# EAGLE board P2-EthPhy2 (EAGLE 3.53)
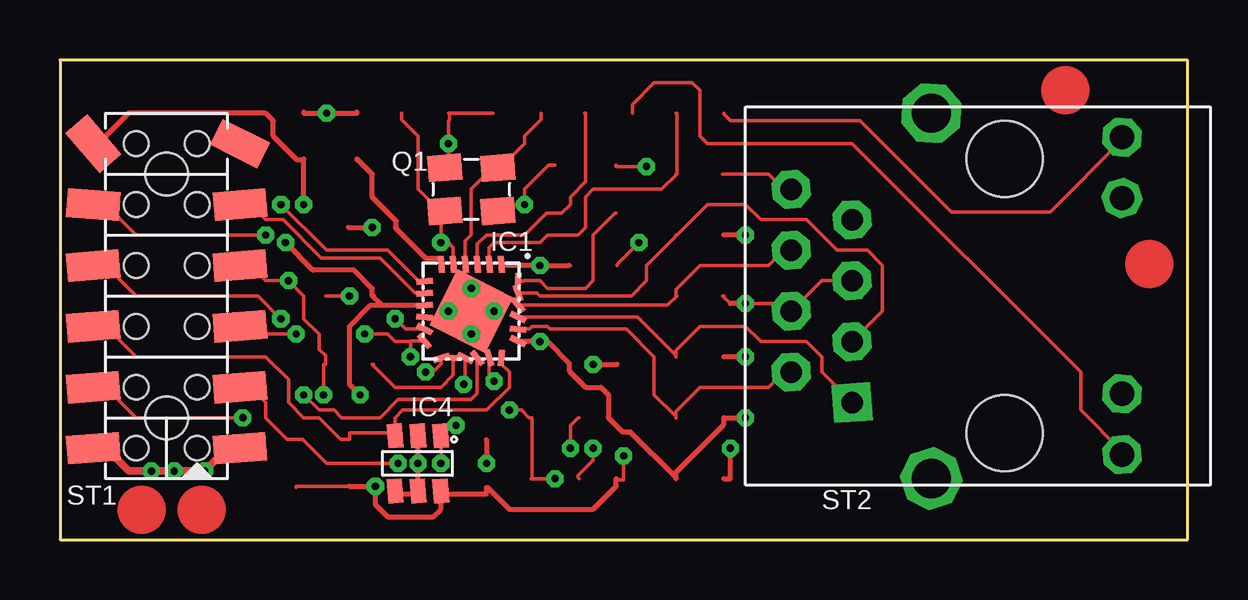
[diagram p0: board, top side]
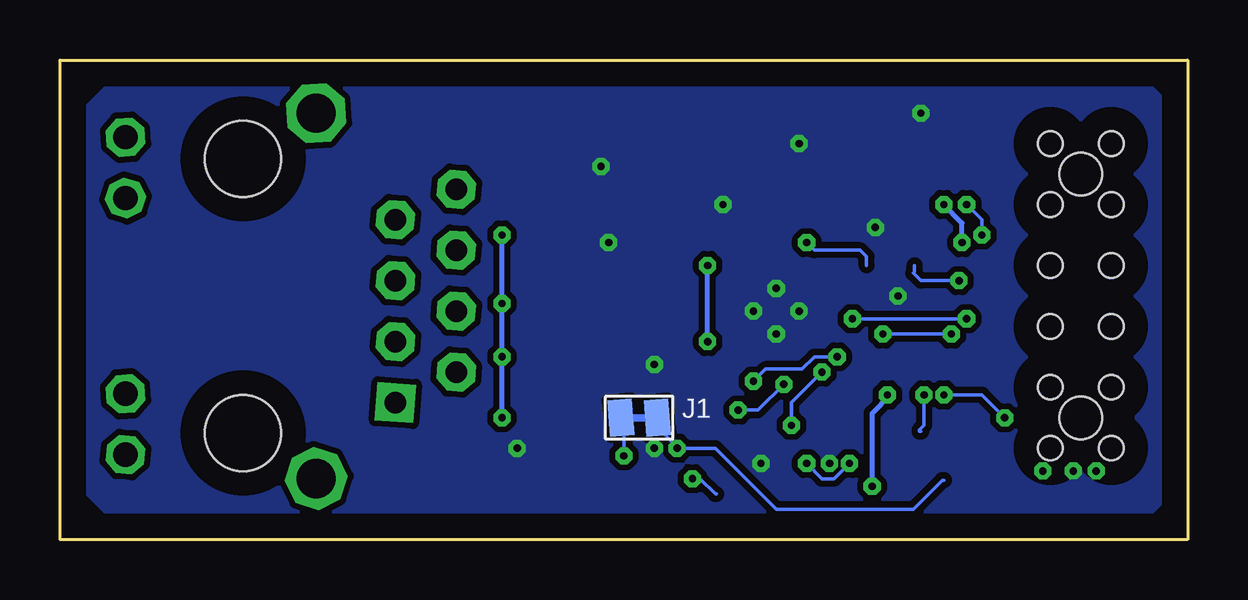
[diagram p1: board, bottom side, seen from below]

Size 47 x 20 mm. Coordinates in mm from the lower left corner, seen from the top.
Outline: 0,0 47,0 47,20 0,20 0,0
Copper layers used: Top, Bottom

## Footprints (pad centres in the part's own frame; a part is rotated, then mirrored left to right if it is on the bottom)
N-24 = smd 2.6 x 2.6 rotated 116.9:  0,0 | smd 0.25 x 0.7 rotated 4.6:  0.25,-1.95 | smd 0.25 x 0.7 rotated 4.5:  -0.25,-1.95 | smd 0.25 x 0.7 rotated 4.4:  -0.75,-1.95 | smd 0.25 x 0.7 rotated 4.3:  -1.25,-1.95 | smd 0.25 x 0.7 rotated 4.7:  0.75,-1.95;  1.25,-1.95 | smd 0.7 x 0.25 rotated 4.8:  1.95,-1.25 | smd 0.7 x 0.25 rotated 4.9:  1.95,-0.75 | smd 0.7 x 0.25 rotated 49.3:  1.95,1.25 | smd 0.7 x 0.25 rotated 26.8:  1.95,0.75 | smd 0.7 x 0.25 rotated 4.3:  1.95,0.25 | smd 0.7 x 0.25 rotated 5:  1.95,-0.25 | smd 0.25 x 0.7 rotated 71.8:  1.25,1.95 | smd 0.25 x 0.7 rotated 94.3:  0.75,1.95 | smd 0.25 x 0.7 rotated 116.8:  0.25,1.95 | smd 0.25 x 0.7 rotated 139.3:  -0.25,1.95 | smd 0.7 x 0.25 rotated 4.4:  -1.95,0.75 | smd 0.7 x 0.25 rotated 206.8:  -1.95,1.25 | smd 0.25 x 0.7 rotated 184.3:  -1.25,1.95 | smd 0.25 x 0.7 rotated 161.8:  -0.75,1.95 | smd 0.7 x 0.25 rotated 26.9:  -1.95,0.25 | smd 0.7 x 0.25 rotated 49.4:  -1.95,-0.25 | smd 0.7 x 0.25 rotated 71.9:  -1.95,-0.75 | smd 0.7 x 0.25 rotated 94.4:  -1.95,-1.25
T23-6 = smd 0.635 x 1.016 rotated 4.7:  0,1.15;  -0.95,1.15 | smd 0.635 x 1.016 rotated 4.6:  0.95,1.15 | smd 0.635 x 1.016 rotated 4.3:  -0.95,-1.15 | smd 0.635 x 1.016 rotated 4.4:  0,-1.15 | smd 0.635 x 1.016 rotated 4.5:  0.95,-1.15
MP2-NC = smd 1.016 x 1.524 rotated 4.3:  -0.762,0 | smd 1.016 x 1.524 rotated 4.4:  0.762,0
D3225 = smd 1.4 x 1.1 rotated 4.6:  -1.1,0.9 | smd 1.4 x 1.1 rotated 4.3:  -1.1,-0.9 | smd 1.4 x 1.1 rotated 4.4:  1.1,-0.9 | smd 1.4 x 1.1 rotated 4.5:  1.1,0.9
06-SBE = smd 1.2 x 2.2 rotated 4.3:  -6.35,-3.058;  3.81,3.058 | smd 1.2 x 2.2 rotated 4.4:  -6.35,3.058 | smd 1.2 x 2.2 rotated 4.5:  -3.81,-3.058 | smd 1.2 x 2.2 rotated 4.6:  -3.81,3.058 | smd 1.2 x 2.2 rotated 4.7:  -1.27,-3.058;  -1.27,3.058 | smd 1.2 x 2.2 rotated 4.8:  1.27,-3.058 | smd 1.2 x 2.2 rotated 4.9:  1.27,3.058 | smd 1.2 x 2.2 rotated 5:  3.81,-3.058 | smd 1.2 x 2.2 rotated 26.8:  6.35,-3.058 | smd 1.2 x 2.2 rotated 49.3:  6.35,3.058 | hole 1.016: -6.35,-1.27; -3.81,-1.27; -1.27,-1.27; 1.27,-1.27; 3.81,-1.27; 6.35,-1.27; 6.35,1.27; 3.81,1.27; 1.27,1.27; -1.27,1.27; -3.81,1.27; -6.35,1.27 | hole 1.778: -5.08,0; 5.08,0
45HR5C = drill 0.89 pad 1.6 octagon:  8.89,0.635;  6.35,1.905;  6.35,-0.635;  8.89,-1.905;  8.89,3.175;  6.35,-3.175;  8.89,-4.445 | drill 0.89 pad 1.6 square:  6.35,4.445 | drill 1.63 pad 2.184 octagon:  3.05,7.62;  3.05,-7.62 | drill 1.016 pad 1.6 octagon:  -4.9,6.62;  -4.9,4.08;  -4.9,-4.08;  -4.9,-6.62 | hole 3.175: 0,5.715; 0,-5.715

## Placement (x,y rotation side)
C1  100n  [05]  20.64,2.54 180 top
C2  15p  [05]  15.24,17.78 180 top
C3  15p  [05]  19.05,17.78 0 top
C4  100n  [05]  26.67,2.54 180 top
C5  10u  [05]  10.16,16.83 270 top
C6  100n  [05]  12.06,10.16 0 top
C7  100n  [05]  22.23,7.3 180 top
C8  100n  [05]  22.23,11.43 180 top
C9  470p  [05]  13.02,13.02 0 top
C10  10u  [05]  12.38,16.83 270 top
C11  100n  [05]  17.78,3.17 270 top
D1  dnp  [T-23]  11.11,3.49 0 bottom
IC1  LAN8720  [N-24]  17.14,9.53 180 top
IC4  24AA025E48  [T23-6]  14.92,3.17 180 top
J1  ResPU  [MP2-NC]  22.86,5.08 180 bottom
L1  FeBead  [05]  23.5,3.49 90 top
Q1  25M  [D3225]  17.14,14.61 0 top
R1  10k  [05]  20.64,5.08 0 top
R2  12k  [05]  23.18,14.61 270 top
R3  27R  [05]  12.06,7.3 180 top
R4  dnp  [05]  12.38,11.43 180 bottom
R5  330R  [05]  22.86,17.78 0 top
R6  330R  [05]  26.67,17.78 0 top
R7  49R9  [05]  26.67,5.08 0 top
R8  49R9  [05]  26.67,7.62 0 top
R9  49R9  [05]  26.67,10.16 0 top
R10  49R9  [05]  26.67,12.7 0 top
R11  10k  [05]  26.67,15.24 180 top
R12  10k  [05]  20.64,14.61 270 top
R13  dnp  [05]  20.64,1.91 0 bottom
R21  10k  [05]  9.84,3.17 90 top
R66  10k  [05]  12.06,3.17 270 top
ST1  P2Eval  [06-SBE]  4.45,10.16 90 top
ST2  RJ45-HR05  [45HR5C]  39.37,10.16 180 top
U$6  [DU-2RM]  5.91,1.25 0 top
U$8  [DU-2RM]  41.91,18.75 0 top
U$9  [DU-2RT]  3.4,1.25 0 top
U$10  [DU-2RT]  45.41,11.5 0 top

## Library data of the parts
C1-C11 D1 L1 R1-R13 R21 R66 = SMD
IC1 IC4 = SMD-IC
J1 U$6 U$8-U$10 = SMD-SPC
Q1 = Quartz
ST1 = PINHEAD
ST2 = CONNECT

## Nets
+3,3V: C5. C6. C11. IC1. IC4. J1. L1. R21. R66. ST1.
/RES: C1. IC1. R1. R13.
C50M: D1. R3. R4. ST1.
CRSDV: IC1. ST1.
ERX+: IC1. R10. ST2.
ERX-: IC1. R9. ST2.
ETX+: IC1. R8. ST2.
ETX-: IC1. R7. ST2.
GND: C1. C2. C3. C4. C5. C6. C7. C8. C9. C10. C11. IC1. IC4. Q1. R2. R11. R12. R13. ST1. ST2.
LEDG: IC1. R5. R12.
LEDY: IC1. R6. R11.
MDC: IC1. IC4. R21. ST1.
N$1: D1. J1. R1.
N$3: R6. ST2.
N$6: R5. ST2.
N$18: C3. IC1. Q1.
N$40: IC1. R2.
RCLK: IC1. R3.
RXD0: IC1. ST1.
RXD1: IC1. ST1.
TXD0: IC1. ST1.
TXD1: IC1. IC4. R66. ST1.
TXEN: IC1. ST1.
VDD: C4. C7. C8. IC1. L1. R7. R8. R9. R10. ST2.
VECR: C9. C10. IC1.
XI25: C2. IC1. Q1. R4.

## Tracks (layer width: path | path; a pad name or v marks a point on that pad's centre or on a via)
+3,3V  (via drill 0.3 pad 0.61)
  Top 0.152: 23.23,2.49 23.5,2.49 v23.5,3.49 | 12.06,2.17 12.06,2.22 9.84,2.22 9.84,2.17
  Top 0.203: 13.02,10.16 13.06,10.16 | 13.4,9.78 15.2,9.78 | 13.4,9.78 13.02,10.16 | 15.88,1.91 17.78,1.91 17.78,2.17 17.83,2.17 18.73,1.27 22.23,1.27 23.18,2.22 23.18,2.54 23.23,2.49 | IC4. 15.87,1.91 15.88,1.91 | 15.88,1.91 15.88,1.27 15.56,0.95 13.65,0.95 13.14,1.46 v13.14,2.22 12.06,2.22 | 13.02,10.16 13.02,10.48 12.26,11.24 10.54,11.24 v9.4,12.38 | v10.16,13.97 10.16,15.88 10.11,15.83 10.16,15.83 9.89,15.83 8.89,16.83 8.89,17.46 8.57,17.78 2.86,17.78 1.59,16.51 ST1. | 13.4,9.78 12.95,9.78 12.06,8.89 12.06,6.48 v12.51,6.03
  Bottom 0.152: J1. 23.5,5.08 v23.5,3.49
  Bottom 0.203: v9.4,12.38 9.4,13.21 v10.16,13.97 | v13.14,2.22 13.14,5.27 12.38,6.03 v12.51,6.03
/RES  (via drill 0.3 pad 0.61)
  Top 0.152: 16.89,7.58 16.89,6.54 v16.83,6.48 | v20.64,2.54 19.64,2.54 19.68,2.54 19.68,5.08 19.64,5.08 19.56,5.08 19.24,5.4 v18.73,5.4
  Bottom 0.152: v18.73,5.4 17.91,5.4 v16.83,6.48 | v20.64,2.54 20.32,2.54 19.68,1.91 19.64,1.91
C50M  (via drill 0.3 pad 0.61)
  Top 0.152: 7.5,11.43 7.94,11.43 8.57,10.79 v9.53,10.79 10.16,10.16 10.16,9.21 10.79,8.57 10.79,7.94 11.06,7.67 11.06,7.3 10.99,7.3 v10.99,6.03
  Bottom 0.152: 11.38,11.43 11.38,11.16 11.43,11.11 11.11,10.79 v9.53,10.79 | 11.11,4.51 11.18,4.51 11.18,4.57 10.99,4.76 v10.99,6.03
CRSDV  (via drill 0.3 pad 0.61)
  Top 0.152: 15.2,8.78 14.4,8.78 v13.97,9.21 | v9.21,9.21 8.26,10.16 3.17,10.16 1.91,11.43 1.39,11.43
  Bottom 0.152: v9.21,9.21 v13.97,9.21
ERX+
  Top 0.152: 33.02,8.26 34.29,9.53 34.29,11.43 33.66,12.06 32.38,12.06 31.11,13.34 29.21,13.34 28.57,13.97 26.99,13.97 25.72,12.7 25.67,12.7 25.67,12.65 24.45,11.43 24.45,10.79 23.81,10.16 20,10.16 19.89,10.28 19.09,10.28
ERX-
  Top 0.152: 30.48,12.06 30.16,12.06 29.53,11.43 26.67,11.43 25.67,10.43 25.67,10.16 25.72,10.16 25.33,9.78 19.09,9.78
ETX+
  Top 0.152: 33.02,5.71 31.75,6.99 31.75,7.62 31.11,8.26 29.21,8.26 28.57,8.89 26.67,8.89 25.67,7.89 25.67,7.62 25.67,7.67 24.06,9.28 19.09,9.28
ETX-
  Top 0.152: 30.48,6.99 30.16,6.99 29.53,6.35 26.67,6.35 25.67,5.35 25.67,5.08 25.67,5.13 24.77,6.03 24.77,7.62 23.61,8.78 20.43,8.78 20.32,8.89 19.68,8.89 19.57,8.78 19.09,8.78
GND  (via drill 0.3 pad 0.61)
  Top 0.152: 16.05,15.51 16.14,15.51 16.19,15.56 v16.19,16.51 16.19,17.46 16.24,17.51 16.24,17.78 | 18.25,13.71 18.47,13.71 18.73,13.97 v19.37,13.97 19.37,14.61 20.37,15.61 20.64,15.61 | 16.24,17.78 16.19,17.78 | 16.24,17.78 18.05,17.78 | 30.48,14.61 30.16,14.61 29.53,15.24 27.67,15.24 27.62,15.24 | 23.18,15.61 23.18,15.56 v24.45,15.56 | 23.23,11.43 23.23,11.48 v24.13,12.38 | 11.06,10.16 v12.06,10.16 | 21.64,2.54 21.59,2.59 21.59,2.67 22.23,3.3 v22.23,3.81
  Top 0.203: v22.23,7.3 23.23,7.3 | 27.67,2.54 27.94,2.54 v27.94,3.81 | 12.02,13.02 v13.02,13.02 | 12.38,17.83 12.38,17.78 v11.11,17.78 10.16,17.78 10.16,17.83 | 14.92,4.33 v14.92,3.17 14.92,2.02 14.92,1.91 13.97,1.91 13.97,2.02 | 17.78,4.17 v17.78,3.17 | 17.14,9.53 v16.19,9.53
  Top 0.305: 1.39,3.81 1.91,3.81 2.86,2.86 v3.81,2.86 v4.76,2.86 v6.03,2.86 6.99,3.81 7.5,3.81
  other vias: 17.14,10.48 18.1,9.53 17.14,8.57
  pour Bottom (isolate 0.254): 1.68,19 0.68,18 0.68,2 1.68,1 44.91,1 45.91,2 45.91,18 44.91,19
LEDG
  Top 0.152: 17.39,11.47 17.39,12.31 17.78,12.7 19.37,12.7 20.27,13.61 20.64,13.61 20.91,13.61 21.27,13.97 21.27,14.29 21.91,14.92 21.91,17.78 21.86,17.78
LEDY
  Top 0.152: 17.89,11.47 17.89,12.18 18.1,12.38 20,12.38 20.32,12.7 21.59,12.7 21.91,13.02 21.91,14.29 22.23,14.61 25.08,14.61 25.72,15.24 | 25.72,15.24 25.67,15.24 | 25.67,17.78 25.72,17.78 25.72,15.24
MDC  (via drill 0.3 pad 0.61)
  Top 0.152: v16.51,4.76 15.88,4.76 15.88,4.45 15.87,4.44 15.87,4.33 15.87,4.13 15.88,4.13 v15.88,3.17 | v15.24,6.99 15.56,6.99 15.89,7.32 15.89,7.58 | v14.1,3.17 11.11,3.17 10.11,4.17 9.84,4.17 9.48,4.17 8.57,5.08 8.57,5.71 7.94,6.35 7.5,6.35
  Bottom 0.152: v16.51,4.76 16.51,5.71 v15.24,6.99 | v14.1,3.17 14.73,2.54 15.24,2.54 v15.88,3.17
N$1  (via drill 0.3 pad 0.61)
  Top 0.152: 21.64,5.08 21.59,5.08 21.27,4.76 v21.27,3.81
  Bottom 0.152: 10.15,2.48 10.22,2.48 11.43,1.27 17.14,1.27 19.68,3.81 v21.27,3.81 21.27,3.87 22.1,4.7 22.1,5.08
N$3
  Top 0.152: ST2. 44.27,16.65 41.27,13.65 37.15,13.65 33.34,17.46 27.94,17.46 27.67,17.73 27.67,17.78
N$6
  Top 0.152: 23.86,17.78 23.86,18.14 24.77,19.05 26.35,19.05 26.67,18.73 26.67,16.83 26.99,16.51 33.02,16.51 42.55,6.99 42.55,5.4 44.27,3.67 44.27,3.54
N$18
  Top 0.152: 16.89,11.47 16.89,12.45 17.14,12.7 17.14,14.61 18.05,15.51 Q1. 18.36,15.51 19.37,16.51 19.37,16.83 20.05,17.51 20.05,17.78
N$40
  Top 0.152: 23.18,13.61 23.13,13.61 22.23,12.7 22.23,10.79 21.91,10.48 20.32,10.48 20,10.79 19.37,10.79 19.35,10.78 IC1.
RCLK
  Top 0.152: 16.39,7.58 16.39,6.87 15.88,6.35 13.97,6.35 13.02,7.3 13.06,7.3
RXD0
  Top 0.152: 15.2,10.28 14.81,10.28 13.34,11.75 10.89,11.75 9.3,13.34 8.57,13.34 7.94,13.97 7.5,13.97
RXD1  (via drill 0.3 pad 0.61)
  Top 0.152: 15.2,10.78 14.94,10.78 13.65,12.06 11.11,12.06 v9.21,13.97 | v8.57,12.7 3.17,12.7 1.91,13.97 1.39,13.97
  Bottom 0.152: v9.21,13.97 8.57,13.34 v8.57,12.7
TXD0  (via drill 0.3 pad 0.61)
  Top 0.152: 17.89,7.58 17.89,6.81 v18.1,6.6 | 14.61,8.26 v14.61,7.62 | 15.2,8.28 14.62,8.28 14.61,8.26 | 14.61,8.26 13.97,8.26 13.65,8.57 v12.7,8.57 | 7.5,8.89 7.49,8.89 7.81,8.57 v9.84,8.57
  Bottom 0.152: v18.1,6.6 17.59,7.11 16.07,7.11 15.56,7.62 v14.61,7.62 | v9.84,8.57 v12.7,8.57
TXD1
  Top 0.152: 18.39,7.58 18.39,7.32 18.73,6.99 18.73,6.35 17.78,5.4 14.29,5.4 13.97,5.08 13.97,4.45 | 13.97,4.33 13.97,4.44 13.97,4.45 | 13.97,4.45 12.06,4.45 12.06,4.17 11.7,4.17 10.79,5.08 10.16,5.08 9.53,5.71 9.53,6.67 8.57,7.62 3.17,7.62 1.91,8.89 1.39,8.89
TXEN  (via drill 0.3 pad 0.61)
  Top 0.152: 17.39,7.58 17.39,6.09 17.14,5.84 14.1,5.84 13.34,5.08 11.75,5.08 11.43,5.4 10.79,5.4 v10.16,6.03 | v7.62,5.08 3.17,5.08 1.91,6.35 1.39,6.35
  Bottom 0.152: v10.16,6.03 8.57,6.03 v7.62,5.08
VDD  (via drill 0.3 pad 0.61)
  Top 0.152: 33.02,10.79 31.75,10.79 30.48,9.53 30.16,9.53 29.84,9.84 v28.57,9.84 | 27.67,10.16 27.62,10.16 27.94,9.84 | 21.23,11.43 21.27,11.43
  Top 0.203: v28.57,5.08 27.67,5.08 27.67,4.81 25.67,2.81 25.67,2.54 25.67,2.59 23.77,4.49 23.5,4.49 23.45,4.49 22.86,5.08 22.86,6.03 22.54,6.35 21.91,6.35 21.23,7.03 21.23,7.3 21.23,7.35 20.32,8.26 v20,8.26 19.98,8.28 19.09,8.28 | v28.57,7.62 27.67,7.62 | v28.57,12.7 27.67,12.7 | v28.57,9.84 27.94,9.84 | 18.39,11.47 18.39,11.45 18.41,11.43 v20,11.43 21.23,11.43
  Bottom 0.203: v28.57,5.08 v28.57,7.62 v28.57,9.84 v28.57,12.7 | v20,8.26 v20,11.43
VECR
  Top 0.203: 15.89,11.47 15.89,11.73 15.26,11.73 13.97,13.02 14.02,13.02 14.02,13.29 13.02,14.29 13.02,15.24 12.38,15.88 12.38,15.83
XI25  (via drill 0.3 pad 0.61)
  Top 0.152: 14.24,17.78 14.24,17.51 14.92,16.83 14.92,14.61 15.82,13.71 16.05,13.71 15.93,13.71 15.88,13.65 v15.88,12.38 16.19,12.38 16.39,12.18 16.39,11.47
  Bottom 0.152: 13.38,11.43 13.38,11.79 13.65,12.06 15.56,12.06 v15.88,12.38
